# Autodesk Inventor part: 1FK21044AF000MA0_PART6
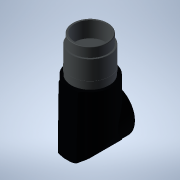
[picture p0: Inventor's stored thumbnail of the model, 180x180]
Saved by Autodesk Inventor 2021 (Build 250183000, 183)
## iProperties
Created: 2025-04
Part Number: 1FK21044AF000MA0_PART6
Material: Generic
Catalog Web Link: www.3dfindit.com
Description: -Servo synchronous motor
Document SubType Name: Modeling
Designer: psAdmin
Mass: 11.0817 g
Surface Area: 35.706 cm^2
Volume: 11.0817 cm^3
Density: 1 g/cm^3
Appearance: PSOLRGB-176-176-176
Category: PARTsolutions
Title: 1FK21044AF000MA0_PART6
Author: Cadenas PARTsolutions
Comments: Servo synchronous motor
Sending System: PARTsolutions
Preprocessor: ST-DEVELOPER v19.3
PSOL_IDENT_0: {$CADENAS_DATA/23d-libs/siemens_ag/_cat_/39/c4/1fk21044af000ma0.prj},213 {VTYP=3D},{NB=1FK21044AF000
PSOL_IDENT_1: MA0_PART6},{LINA=1FK21044AF000MA0_PART6},{NN=1FK21044AF000MA0_PART6},{NOPRJ=TRUE},{DATE=19.08.2025 1
PSOL_IDENT_2: 4:00:33},{GEOMDATE=30.07.2025 02:02:22},{VERSION=},{LINEID=10},{WBVAR=},{WBNUMERIC=}  {NB=1FK21044AF
PSOL_IDENT_3: 000MA0_PART6},{LINA=1FK21044AF000MA0_PART6},{KT=DUMMY},{PREVIEW=../../../_pool_/cb/72/p_d211_xx_0043
PSOL_IDENT_4: 4j.png},{DESCSHORT=SIMOTICS S-1FK2 HD, SINAMICS S210 3AC 400V-480V, 1.27 Nm, 3000 rpm},{DESCLONG=SIM
PSOL_IDENT_5: OTICS S-1FK2 HD servo motor M0=1.27 Nm; PN = 0.4 kW at nN=3000 rpm (380-480 V); PN = 0.2 kW at nN=15
PSOL_IDENT_6: 00 rpm (200-240 V); degree of protection IP64; cylindrical shaft D19x40mm; absolute encoder 22-bit +
PSOL_IDENT_7: 12-bit multiturn (encoder AM22DQC); with OCC interface; plug size M17, rotatable; SIMOTICS S-1FK2 s
PSOL_IDENT_8: ervomotorfor a wide range of uses in industrial environments. SIMOTICS S‑1FK2 servomotors are compac
PSOL_IDENT_9: t synchronous motors with a high dynamic performance that set themselves apart as a result of their
PSOL_IDENT_10: high power density, degree of protection and overload capability. The motors are available in two va
PSOL_IDENT_11: riants: as High Dynamic variant (highest dynamic performance as a result of the low intrinsic moment
PSOL_IDENT_12: of inertia for applications demanding a high dynamic performance with low moved masses) - and as Co
PSOL_IDENT_13: mpact variant (precise and stable closed-loop control for medium up to large moved masses as a resul
PSOL_IDENT_14: t of a medium intrinsic moment of inertia). SIMOTICSS‑1FK2 servomotors fully exploit their strengths
PSOL_IDENT_15: in a system with the SINAMICSS210 frequency converter and simple connection using the one cable con
PSOL_IDENT_16: nection (OCC). Advantages include the short control and positioning times, fast and precise correcti
PSOL_IDENT_17: on of disturbing quantities as well as stable control with a high dynamic performance. The servo mot
PSOL_IDENT_18: ors can be configured to address a wide range of requirements. For example with and without holding
PSOL_IDENT_19: brake, IP64 or IP65 degree of protection, singleturn or multiturn absolute encoders - to name just a
PSOL_IDENT_20: few. Further, the servomotors are available in different shaft heights extending from 20 to 100. A
PSOL_IDENT_21: shaft sealing ring is available to achieve an IP65 degree of protection and for subsequent mounting
PSOL_IDENT_22: at the motor or as spare part. SIMOTICS - the optimum motor for each and every motion control applic
PSOL_IDENT_23: ation.},{INTNO=804766906428},{SUPPLIERALTNO=1FK2104-4AF00-0MA0},{MANUID=1FK21044AF000MA0},{MANUNAME=
PSOL_IDENT_24: Siemens},{MANUTYPEDESC=Synchronous motor 1FK2-HD 1.27 NM},{AAU732=SIMOTICS},{AAO057=S-1FK2},{AAU734=
PSOL_IDENT_25: SIMOTICS S-1FK2 HD servo motor M0=1.27 Nm; PN = 0.4 kW at nN=3000 rpm (380-480 V); PN = 0.2 kW at nN=
PSOL_IDENT_26: 1500 rpm (200-240 V); degree of protection IP64; cylindrical shaft D19x40mm; absolute encoder 22-bit
PSOL_IDENT_27: + 12-bit multiturn (encoder AM22DQC); with OCC interface; plug size M17, rotatable;},{AAW338=Synchr
PSOL_IDENT_28: onous motor 1FK2-HD 1.27 NM},{AAO742=SIMOTICS},{AAO663=4042948693322},{NOCUPEROU=1},{PRICEQUANTITY=1
PSOL_IDENT_29: },{QUANTITYMIN=1},{QUANTITYINT=1},{CTN=85015100},{COO=DE},{AAO676=1FK2104-4AF00-0MA0},{AAO677=Siemen
PSOL_IDENT_30: s AG},{ORDERUNIT=C62},{CONTENTUNIT=C62}
NB: 1FK21044AF000MA0_PART6
NT: Servo synchronous motor
NBSYN: $MANUID._PART6
LINA: 1FK21044AF000MA0_PART6
CATALOG: SIEMENS
PREVIEW: ../../../_pool_/cb/72/p_d211_xx_00434j.png
DESCSHORT: SIMOTICS S-1FK2 HD, SINAMICS S210 3AC 400V-480V, 1.27 Nm, 3000 rpm
DESCLONG: SIMOTICS S-1FK2 HD servo motor M0=1.27 Nm; PN = 0.4 kW at nN=3000 rpm (380-480 V); PN = 0.2 kW at nN=1500 rpm (200-240 V); degree of protection IP64; cylindrica
INTNO: 804766906428
SUPPLIERALTNO: 1FK2104-4AF00-0MA0
MANUID: 1FK21044AF000MA0
MANUNAME: Siemens
MANUTYPEDESC: Synchronous motor 1FK2-HD 1.27 NM
AAU732: SIMOTICS
AAO057: S-1FK2
AAU734: SIMOTICS S-1FK2 HD servo motor M0=1.27 Nm; PN = 0.4 kW at nN=3000 rpm (380-480 V); PN = 0.2 kW at nN=1500 rpm (200-240 V); degree of protection IP64; cylindrica
AAW338: Synchronous motor 1FK2-HD 1.27 NM
AAO742: SIMOTICS
AAO663: 4042948693322.0
NOCUPEROU: 1
PRICEQUANTITY: 1
QUANTITYMIN: 1
QUANTITYINT: 1
CTN: 85015100
COO: DE
ARTICLENO: 1FK21044AF000MA0_PART6
BOMINFO: 1FK21044AF000MA0_PART6
CREATOR: CADENAS GmbH
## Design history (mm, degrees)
feature "2025_04_17_15_01_28_0007"
body "Solid1"
